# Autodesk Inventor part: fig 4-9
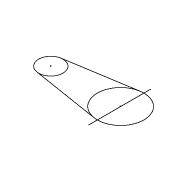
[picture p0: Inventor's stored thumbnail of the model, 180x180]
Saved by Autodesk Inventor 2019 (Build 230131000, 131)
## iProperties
Created: 2005-02
Part Number: fig 4-9
Document SubType Name: Modeling
Designer: CADCIM
Manufacturer: Standard
Standards Organization: Custom
Density: 1 g/cm^3
Material: Generic
Appearance: Default
Author: CADCIM
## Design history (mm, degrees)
sketch "Sketch1"
  geometry: L1 (-28.496, 15.735)-(10.446, 21.986); L2 (-28.503, 2.004)-(10.432, -4.291); L3 (12.58, 26.117)-(12.58, -9.642); A1 r 6.954 centre (-27.393, 8.869) between (-28.496, 15.735) and (-28.503, 2.004); A2 r 13.308 centre (12.555, 8.846) between (10.446, 21.986) and (10.432, -4.291)
  constraints: 6 end point, 4 point on circle, 4 tangent, 2 centre point, 1 vertical, 1 other
